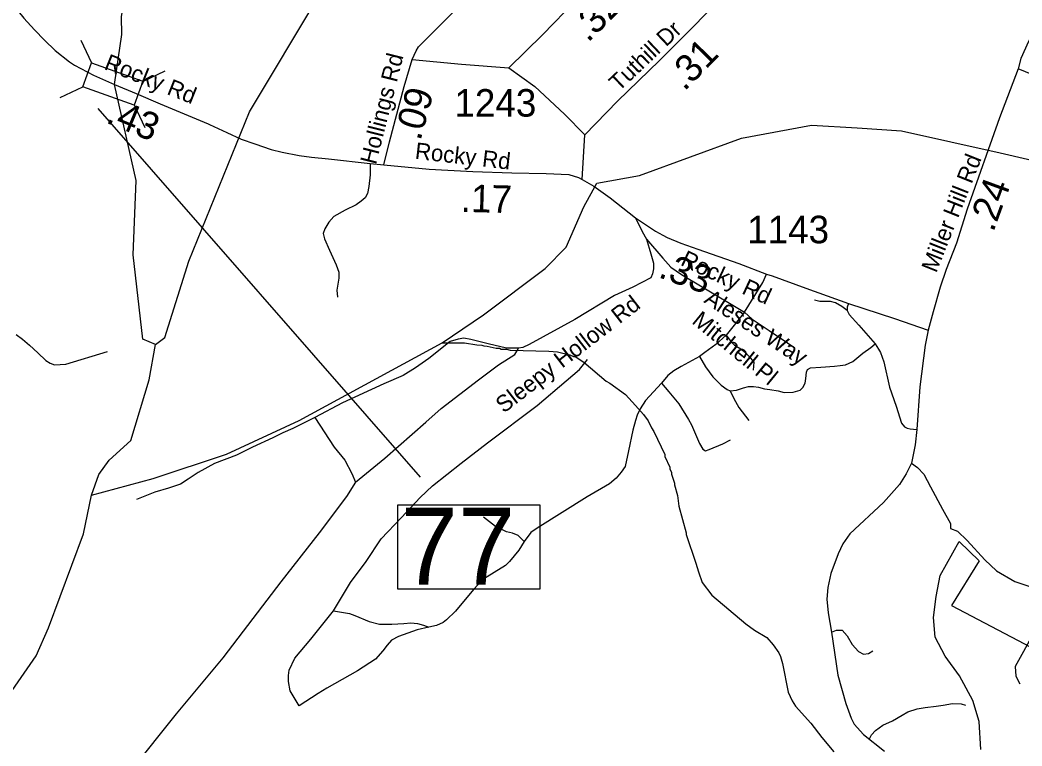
# Model space of a CAD drawing. Extents: x 1159738 to 1321356, y 736314 to 882035.
# Drawn here: x 1230616 to 1235163, y 776906 to 780200 of the extents above; entities that cross this region are included whole.
import ezdxf

# ---------------------------------------------------------------- set-up
doc = ezdxf.new("R2010")
doc.units = 0
for name, color, linetype in [('Exist Boundary Political City Limit New InsideOut', 7, 'Continuous'), ('Exist Hydrographic Creek Single Shore', 7, 'Continuous'), ('Exist Hydrographic Misc Water Feature', 7, 'Continuous'), ('Exist Road Non-System Type 51', 7, 'Continuous'), ('Exist Road Non-System Type 51 Label', 7, 'Continuous'), ('Exist Road Secondary Mileage Hundredths English Label', 7, 'Continuous'), ('Exist Road Secondary Structure Standard Bridge CELL', 7, 'Continuous'), ('Exist Road Secondary Structure Standard Bridge Number Label', 7, 'Continuous'), ('Exist Road Secondary Type 51 Attributed', 7, 'Continuous'), ('Exist Road Secondary Type 51 Label', 7, 'Continuous'), ('Exist Road Secondary Type 51 Number Label', 7, 'Continuous')]:
    doc.layers.add(name, color=color, linetype=linetype)

msp = doc.modelspace()

# ---------------------------------------------------------------- linework, layer by layer
at = {"layer": 'Exist Boundary Political City Limit New InsideOut'}
msp.add_lwpolyline([(1234976.7, 776889.7), (1234969.6, 777016.6), (1234940.6, 777111.9), (1234880.6, 777223.5), (1234814.7, 777313.9), (1234769.7, 777398.9), (1234761.6, 777488.8), (1234774.6, 777583.8), (1234792.9, 777678.7), (1234877.8, 777833), (1234968.9, 777745.3), (1234843.5, 777542.5), (1235474.7, 777212.1), (1235818.1, 777667.4), (1236519.5, 777441.3), (1236694, 777529.2), (1237870.5, 777461.3), (1237857, 776313.9)], dxfattribs=at)
at = {"layer": 'Exist Hydrographic Creek Single Shore'}
for points in [[(1231231, 778728), (1231273.1, 778760), (1231382.1, 779105.8), (1231658.1, 779783), (1231971.8, 780310.3), (1232137, 780564.5), (1232326, 781099), (1232568, 781452), (1232699.7, 781702.3), (1232787.7, 781874.5), (1232956.2, 782327.5), (1233027.1, 782807)], [(1231077.5, 780134.7), (1231077, 780214.8), (1231130.1, 780564)], [(1231044.3, 779908.1), (1231077.5, 780134.7)], [(1231231, 778728), (1231173, 778752.1), (1231129.1, 779134.6), (1231143.6, 779471.9), (1231044.3, 779908.1)], [(1230940.1, 778043.9), (1231220.4, 778119.9), (1231552.6, 778230.8), (1231882.5, 778383.1), (1232532.6, 778734.8), (1232718.9, 778863), (1232999.4, 779072.8), (1233094.6, 779169.7), (1233175.5, 779352.4), (1233234.3, 779460.4), (1233427, 779494.7), (1233890.2, 779664.6), (1234208, 779722.4), (1234416, 779711.3), (1234616, 779697.5), (1235063.9, 779597.2), (1235645.3, 779462.8)], [(1230940.1, 778043.9), (1230973, 778137.6), (1231020.2, 778203.1), (1231119, 778291.7), (1231202, 778567.7), (1231231, 778728)], [(1230580.1, 777157.5), (1230689.2, 777315.1), (1230744.7, 777442.4), (1230904.1, 777868.8), (1230940.1, 778043.9)]]:
    msp.add_lwpolyline(points, dxfattribs=at)
at = {"layer": 'Exist Hydrographic Misc Water Feature'}
msp.add_lwpolyline([(1232532.6, 778734.8), (1232632.9, 778736), (1232688.6, 778726.7), (1232712.6, 778725.4), (1232720.5, 778721.9), (1232736.6, 778720.8), (1232776.3, 778711.8), (1232792.3, 778711.5), (1232800.2, 778707.2), (1232824.2, 778706.7), (1232840.1, 778702.3), (1233016.1, 778697.9), (1233056.1, 778694.7), (1233111.8, 778681.3), (1233127.6, 778672.7), (1233135.6, 778672.6), (1233174.9, 778648), (1233276.7, 778561.4), (1233292.5, 778552.9), (1233363.4, 778500.6), (1233410, 778451.3), (1233445, 778410.4), (1233466.3, 778382), (1233481.5, 778349.7), (1233493, 778333.1), (1233542.4, 778227.9), (1233542.2, 778219.7), (1233564.9, 778171.6), (1233564.7, 778163.4), (1233572.3, 778146.8), (1233572.1, 778139.4), (1233587.1, 778098.9), (1233586.9, 778090.7), (1233599.6, 778042), (1233606.4, 777994.3), (1233639.3, 777873), (1233639.1, 777865.6), (1233683.8, 777735.9), (1233694.7, 777695.5), (1233711.5, 777647.6), (1233756.1, 777590.1), (1233910.8, 777459.7), (1233950.1, 777431), (1234005.2, 777397.9), (1234034.4, 777364.5), (1234059.5, 777327.9), (1234067.1, 777312.2), (1234076.3, 777280), (1234102.9, 777150.6), (1234120, 777110), (1234135.3, 777085.9), (1234205.3, 777009.9), (1234255.8, 776944.9), (1234310.1, 776879.8)], dxfattribs=at)
at = {"layer": 'Exist Road Non-System Type 51'}
for points in [[(1232834, 779983.3), (1232952.2, 779898.8), (1233087.8, 779772.7), (1233179.7, 779679.9)], [(1232204.5, 779549.6), (1232205.4, 779497.1), (1232198.7, 779445.2), (1232192.9, 779412.4), (1232182.4, 779394.1), (1232165, 779378.7), (1232141, 779361.4), (1232091, 779337.3), (1232040.9, 779308.5), (1232017.9, 779282.5), (1231998.6, 779252.6), (1231991.9, 779231.5), (1231997.7, 779207.4), (1232019.8, 779155.4), (1232051.5, 779089.1), (1232063.1, 779056.4), (1232063.1, 779028.5), (1232054.4, 778975), (1232057.3, 778943.3)], [(1233409, 779302.4), (1233439, 779240.7), (1233459.5, 779205.2)], [(1233459.5, 779205.2), (1233478.7, 779139.5), (1233491.4, 779096.7), (1233491.4, 779071.2), (1233486.6, 779049), (1233478.7, 779029.9), (1233397.8, 778988.6), (1233313.6, 778950.5), (1233134.3, 778840.9), (1232926.4, 778728.2), (1232898.3, 778714.6), (1232877.7, 778711.4)], [(1233459.5, 779205.2), (1233533.7, 779119.9), (1233570.1, 779078.8), (1233618.2, 779044.8), (1233712.2, 778989.5), (1233904.5, 778874.5)], [(1233904.5, 778874.5), (1233986.6, 779009.6), (1234004, 779047.6)], [(1234370.6, 778881.7), (1234345.4, 778900.6), (1234316.9, 778917.2), (1234294, 778923.5), (1234270.3, 778922.7), (1234246.7, 778922.7), (1234221.4, 778929.1)], [(1234375.8, 778913.8), (1234370.6, 778896.7), (1234370.6, 778881.7), (1234379.3, 778864.3), (1234422.7, 778815.3), (1234497, 778730.3)], [(1233904.5, 778874.5), (1233820.9, 778770.5)], [(1233904.5, 778874.5), (1233939.6, 778842.2), (1234015.4, 778791.6), (1234099.9, 778735.5), (1234132.3, 778712.6)], [(1232877.7, 778711.4), (1232823.7, 778711.4), (1232741.2, 778730.5), (1232661.8, 778751.1), (1232630.1, 778755.9), (1232604.7, 778752.7), (1232568.2, 778741.6), (1232471.3, 778663.8), (1232411, 778622.5), (1232355.5, 778587.5), (1232266.6, 778549.4), (1232079.3, 778463.7), (1231954.5, 778395.9)], [(1233820.9, 778770.5), (1233774.3, 778727), (1233724.6, 778691.5), (1233699.3, 778673.3)], [(1233820.9, 778770.5), (1233839.6, 778746.3), (1233859.3, 778724.2), (1233886.9, 778707.6), (1233909, 778691), (1233931.9, 778665.7), (1233946.2, 778648.3), (1233943, 778612)], [(1232138.6, 778103.6), (1232272, 778211.6), (1232457.7, 778375.2), (1232527.5, 778437.2), (1232697.3, 778567.4), (1232787.8, 778635.7), (1232861.9, 778682.9), (1232871.4, 778697.2), (1232877.7, 778711.4)], [(1233839, 778517.2), (1233868, 778520.4), (1233898.8, 778530.7), (1233921.7, 778537), (1233945.4, 778537), (1233967.5, 778533.8), (1233995.2, 778525.9), (1234019.6, 778523.5), (1234056.7, 778517.2), (1234084.4, 778510.1), (1234125.4, 778511.7), (1234157, 778521.2), (1234169.6, 778532.2), (1234179.1, 778552.8), (1234182.3, 778573.3), (1234185.4, 778602.6), (1234190.1, 778615), (1234204.3, 778622.1), (1234250.1, 778625.2), (1234313.2, 778630), (1234338.5, 778633.1), (1234362.2, 778635.5), (1234395.3, 778650.5), (1234441.1, 778687.7), (1234477.5, 778713.7), (1234497, 778730.3)], [(1234497, 778730.3), (1234511.7, 778706.8), (1234521.2, 778691), (1234536.2, 778649.2), (1234562.2, 778534.6), (1234592.2, 778448.5), (1234616.7, 778371), (1234630.1, 778354), (1234641.9, 778348.5), (1234656.1, 778344.5), (1234686.9, 778341.3)], [(1232038.8, 777519.5), (1232115.4, 777648.3), (1232186.5, 777743.1), (1232255, 777845.2), (1232346.6, 777942.4), (1232431.9, 778034), (1232488.7, 778086.2), (1232618, 778189.3), (1232737.2, 778281.7), (1232962.8, 778450.3), (1233094.6, 778562.5), (1233155.1, 778614.3), (1233191.4, 778659.3)], [(1233699.3, 778673.3), (1233616.4, 778628.3), (1233582.7, 778608.9), (1233556.6, 778586.8), (1233527.4, 778552)], [(1233699.3, 778673.3), (1233726.9, 778626.2), (1233760.1, 778580.4), (1233798.8, 778543.3), (1233825.6, 778523.5), (1233839, 778517.2)], [(1233527.4, 778552), (1233454.8, 778473), (1233431.1, 778435.1), (1233416.9, 778407.5), (1233409, 778383), (1233397.9, 778339.5), (1233377.5, 778245.2), (1233362.5, 778174.8), (1233344.4, 778148.8), (1233322.3, 778121.1), (1233291.5, 778095), (1233189.6, 778036.6), (1232963.3, 777893.9), (1232934.1, 777875.2), (1232903.4, 777834.1)], [(1233527.4, 778552), (1233561.4, 778512.6), (1233605.6, 778458.9), (1233650.6, 778387), (1233664, 778363.3), (1233700.3, 778278.7), (1233715.2, 778252.1), (1233727, 778245), (1233743.6, 778251.3), (1233805.2, 778277.4), (1233840.7, 778294.8)], [(1233839, 778517.2), (1233856.4, 778482.5), (1233878.5, 778442.2), (1233923.5, 778382.1)], [(1231954.5, 778395.9), (1231854.8, 778346.8), (1231808.8, 778326.2), (1231762.7, 778303.9), (1231670.7, 778261.1), (1231597.7, 778226.1), (1231499.3, 778188), (1231424.7, 778146.7), (1231378.6, 778116.5), (1231343.7, 778094.3), (1231289.8, 778075.2), (1231227.9, 778057.7), (1231145.3, 778024.4)], [(1231954.5, 778395.9), (1232041.8, 778262.4), (1232089.4, 778202.1), (1232121.2, 778141.7), (1232138.6, 778103.6)], [(1234661.7, 778189.2), (1234689.2, 778169.9), (1234717.4, 778138.8), (1234748.6, 778082.2), (1234802.3, 777980.3), (1234839.1, 777915.2), (1234839.1, 777892.6), (1234870.2, 777881.2), (1234915.4, 777838.8), (1234994.6, 777751), (1235048.4, 777700.1), (1235130.4, 777652), (1235235, 777618), (1235243.5, 777575.6), (1235235, 777510.5), (1235232.2, 777459.5), (1235223.7, 777431.2), (1235170, 777335), (1235133.2, 777267.1), (1235136, 777221.8), (1235153, 777187.8)], [(1232138.6, 778103.6), (1232097.7, 778037.8), (1231973.9, 777872.6), (1231799.3, 777650.2), (1231672.4, 777483.8), (1231535.9, 777305.9), (1231325, 777051), (1231120.2, 776795.3), (1230991.9, 776640.2)], [(1232903.4, 777834.1), (1232877.3, 777861), (1232851.2, 777871.2), (1232824.4, 777878.3), (1232774.7, 777902), (1232720.2, 777944.7)], [(1232903.4, 777834.1), (1232880.5, 777793.9), (1232837.1, 777743.4), (1232819.7, 777725.2), (1232767.6, 777693.6), (1232717.1, 777662), (1232673.6, 777615.4), (1232591.8, 777517), (1232551.5, 777478.3), (1232536.5, 777465.6), (1232506.5, 777453), (1232471.2, 777445.3)], [(1231882.6, 777087.9), (1231842.4, 777156.6), (1231834.5, 777197.7), (1231834.5, 777226.1), (1231836.8, 777249.9), (1231863.7, 777303.6), (1231936.3, 777390.5), (1232038.8, 777519.5)], [(1232038.8, 777519.5), (1232111.5, 777506.8), (1232136, 777497.4), (1232200.7, 777471.3), (1232247.3, 777458.7), (1232303.3, 777458.7), (1232357.8, 777461.8), (1232389.4, 777465), (1232419.4, 777461.8), (1232447.8, 777453.9), (1232471.2, 777445.3)], [(1232471.2, 777445.3), (1232419.1, 777432.7), (1232333.8, 777401.9), (1232301.4, 777385.3), (1232282.5, 777363.9), (1232262.7, 777337.9), (1232229.9, 777299.4), (1232147.8, 777247.3), (1232008.8, 777168.3), (1231968.5, 777144.6), (1231882.6, 777087.9)], [(1234299.6, 777422.3), (1234322, 777430.7), (1234347.5, 777430.7), (1234370.1, 777405.2), (1234392.7, 777365.6), (1234421, 777334.5), (1234443.6, 777323.1), (1234466.3, 777326), (1234486, 777337.3)], [(1234470.1, 776934.8), (1234480.8, 776956.2), (1234498.9, 776975.9), (1234531.3, 776999.6), (1234575.5, 777020.1), (1234619.7, 777046.2), (1234645.8, 777060.4), (1234688.4, 777073.9), (1234724, 777081), (1234774.5, 777086.5), (1234805.3, 777091.3), (1234848.7, 777098.4), (1234887.4, 777096.8), (1234907.1, 777090.5)]]:
    msp.add_lwpolyline(points, dxfattribs=at)
at = {"layer": 'Exist Road Secondary Structure Standard Bridge CELL'}
for p, q in [((1230891.7, 780108.6), (1230939.9, 780006.2)), ((1231172.9, 779921.7), (1231275.3, 779969.9)), ((1230798.2, 779849.1), (1230900.6, 779897.3)), ((1231134.6, 779815.3), (1231182.8, 779712.9))]:
    msp.add_line(p, q, dxfattribs=at)
msp.add_lwpolyline([(1230939.9, 780006.2), (1231173.1, 779922.3), (1231133.9, 779813.3), (1230900.6, 779897.3)], close=True, dxfattribs=at)
at = {"layer": 'Exist Road Secondary Structure Standard Bridge Number Label'}
msp.add_line((1230968.8, 779798.6), (1232431.9, 778126.4), dxfattribs=at)
msp.add_lwpolyline([(1232330.6, 778000.4), (1232974.8, 778000.4), (1232974.8, 777618.1), (1232330.6, 777618.1)], close=True, dxfattribs=at)
at = {"layer": 'Exist Road Secondary Type 51 Attributed'}
for points in [[(1235830.2, 781705.7), (1235802.4, 781664.2), (1235762.2, 781582.8), (1235723.2, 781494.3), (1235673.3, 781345.7), (1235658.4, 781289.7), (1235640.4, 781215.5), (1235616.4, 781115.1), (1235586.7, 780974.6), (1235571.9, 780915.4), (1235550.8, 780835.2), (1235524.9, 780751), (1235495.2, 780668.4), (1235468.6, 780602.1), (1235443.3, 780544.6), (1235405.6, 780468.1), (1235370.4, 780400), (1235317.8, 780315.9), (1235293.8, 780278.4), (1235238.1, 780187.6), (1235192.4, 780102.8), (1235159, 780026), (1235145.8, 779979.2)], [(1232395.8, 780021.9), (1232414, 780061), (1232425.1, 780078.3), (1232485.1, 780139.1), (1232931, 780586.7), (1232978.8, 780633.2), (1233113.5, 780772.7), (1233346.1, 781014), (1233359, 781024.4), (1233376.8, 781038.6), (1233393.6, 781042.5), (1233408.3, 781041.7)], [(1233167.7, 779476.6), (1233179.7, 779679.9), (1233327.9, 779832.3), (1233518.5, 780016.7), (1233680.2, 780179.1), (1233824.4, 780330.1), (1233972, 780480), (1234148.7, 780659), (1234168.3, 780687.9)], [(1230351.3, 780572.6), (1230443.9, 780447.7), (1230575.6, 780280.1), (1230632.9, 780209.2), (1230681.3, 780155.5), (1230727, 780108.9), (1230775.6, 780062.3), (1230841, 780010.3), (1230863.9, 779995.6), (1230950.1, 779949.9), (1231044.3, 779908.1)], [(1232395.8, 780021.9), (1232619.9, 779999.4), (1232834, 779983.3), (1232987.5, 780132.6), (1233140.3, 780290.8), (1233299, 780448.4)], [(1232267, 779542.9), (1232292.7, 779646.8), (1232359.1, 779899), (1232395.8, 780021.9)], [(1235145.8, 779979.2), (1235061.3, 779756.5), (1234914.2, 779342.2), (1234865.6, 779187.5), (1234820, 779067.9), (1234792.2, 778988.5), (1234760.4, 778875.9), (1234737.3, 778793.1)], [(1235396.6, 779875.3), (1235145.8, 779979.2)], [(1231044.3, 779908.1), (1231142.3, 779866.2), (1231252.1, 779820.6), (1231469.4, 779729.2), (1231475.2, 779726.6), (1231554.7, 779689.5), (1231620.1, 779660.1), (1231681.7, 779638.9), (1231756.2, 779613.2), (1231805.6, 779600.6), (1231882.2, 779586.2), (1231939, 779578.5), (1232015.9, 779569.8), (1232204.5, 779549.6), (1232267, 779542.9)], [(1232267, 779542.9), (1232472.6, 779523.5), (1232670.7, 779513), (1232848.3, 779506.5), (1233004.1, 779503.6), (1233106.1, 779499.8), (1233150.4, 779485.3), (1233167.7, 779476.6)], [(1233167.7, 779476.6), (1233220.3, 779446.1), (1233294.6, 779393.8), (1233409, 779302.4), (1233500.5, 779241.5), (1233533.3, 779224.5), (1233553.8, 779213.8), (1233615.7, 779188), (1233691.8, 779160.3), (1233877.8, 779094.7), (1234004, 779047.6), (1234029.4, 779039.8), (1234182.7, 778984), (1234375.8, 778913.8), (1234584.4, 778846.1), (1234737.3, 778793.1)], [(1230597.7, 778773.4), (1230627.4, 778751.5), (1230659.5, 778724.9), (1230697, 778689.2), (1230733.8, 778654.6), (1230752.9, 778643), (1230773.1, 778636.1), (1230824.2, 778638.4), (1231013.3, 778696.1)], [(1234737.3, 778793.1), (1234723.9, 778724.8), (1234699.5, 778535.7), (1234686.9, 778341.3), (1234678.2, 778272.1), (1234661.7, 778189.2), (1234637.2, 778140.2), (1234607.2, 778092.8), (1234534.7, 778011), (1234381.6, 777869), (1234350.8, 777822.4), (1234329.5, 777778.2), (1234296.4, 777688.1), (1234283, 777625.1), (1234277.5, 777572.2), (1234283.8, 777510), (1234299.6, 777422.3), (1234327.2, 777227.5), (1234363.5, 777098), (1234388, 777032), (1234401.4, 777005.1), (1234444, 776957.7), (1234539.5, 776882.9)]]:
    msp.add_lwpolyline(points, dxfattribs=at)

# ---------------------------------------------------------------- texts
at = {"layer": 'Exist Road Non-System Type 51 Label'}
for s, rotation, p in [('Sleepy Hollow Rd', 37.6897, (1232811.4, 778413.2)), ('Aleses Way', 326.6343, (1233716, 778920.7)), ('Mitchell Pl', 320.8111, (1233661, 778826.9))]:
    msp.add_text(s, height=75, rotation=rotation, dxfattribs=at).set_placement(p)
at = {"layer": 'Exist Road Secondary Mileage Hundredths English Label'}
for s, rotation, p in [('.32', 45.0223, (1233193.9, 780095.2)), ('.31', 45.7554, (1233631.4, 779874.1)), ('.09', 74.6351, (1232433, 779648.7)), ('.43', 337.4288, (1231000.6, 779736.5)), ('.17', 358.4774, (1232615, 779330)), ('.24', 69.9235, (1235033.1, 779234.1)), ('.33', 340.0793, (1233508.3, 779034.5))]:
    msp.add_text(s, height=125, rotation=rotation, dxfattribs=at).set_placement(p)
at = {"layer": 'Exist Road Secondary Structure Standard Bridge Number Label'}
msp.add_text('77', height=350, dxfattribs=at).set_placement((1232343.2, 777637.9))
at = {"layer": 'Exist Road Secondary Type 51 Label'}
for s, rotation, p in [('Tuthill Dr', 43.4108, (1233333.5, 779873)), ('Rocky Rd', 338.2569, (1230993.2, 779978.6)), ('Hollings Rd', 75.811, (1232231.2, 779541)), ('Rocky Rd', 353.4429, (1232405.9, 779570.8)), ('Miller Hill Rd', 68.3757, (1234774.2, 779049.5)), ('Rocky Rd', 335.1298, (1233609.3, 779089.7))]:
    msp.add_text(s, height=75, rotation=rotation, dxfattribs=at).set_placement(p)
at = {"layer": 'Exist Road Secondary Type 51 Number Label'}
for s, p in [('1243', (1232587.4, 779761.8)), ('1143', (1233916.1, 779187.1))]:
    msp.add_text(s, height=125, dxfattribs=at).set_placement(p)

doc.saveas('drawing.dxf')
